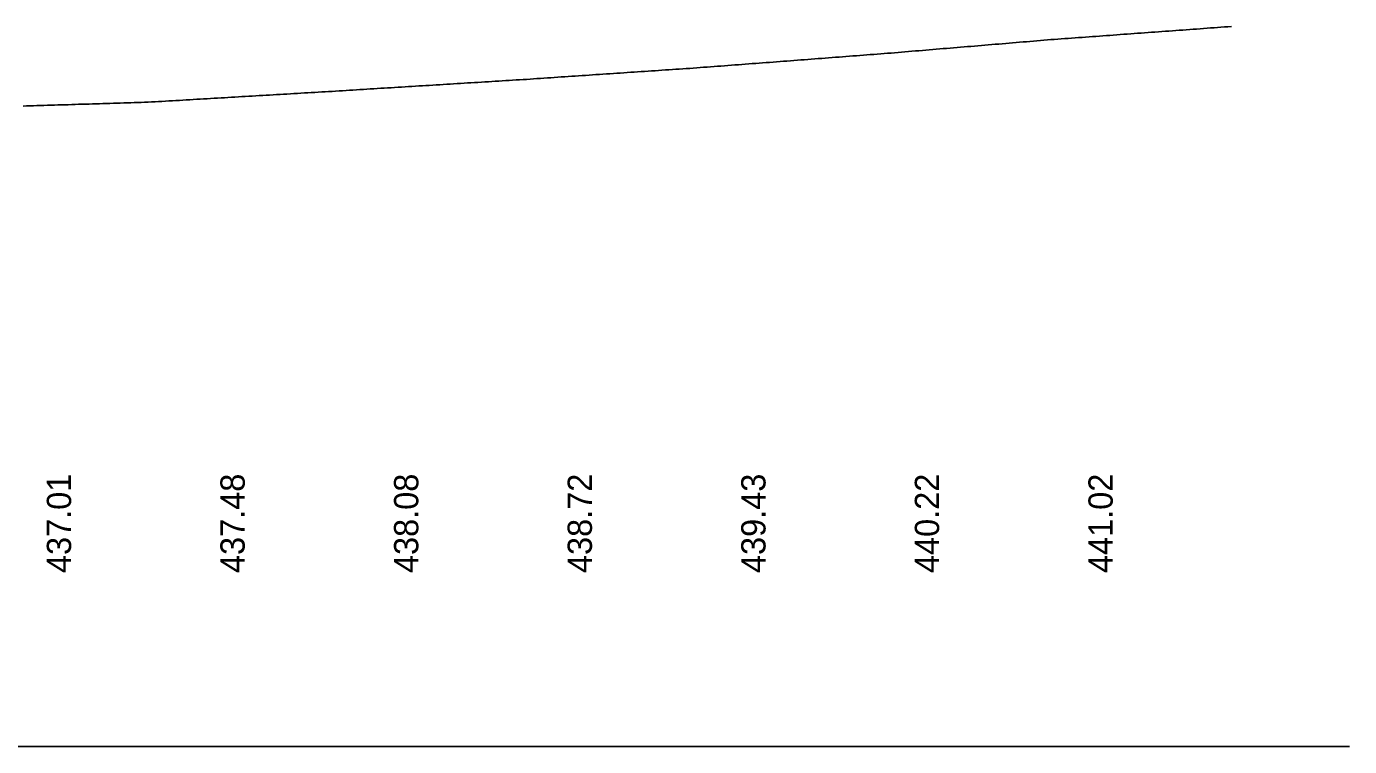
# Model space of a CAD drawing. Extents: x 1904865 to 1906752, y 1106408 to 1110518.
# Drawn here: x 1906371.1 to 1906752.2, y 1107657.6 to 1107865.1 of the extents above; entities that cross this region are included whole.
import ezdxf

# ---------------------------------------------------------------- set-up
doc = ezdxf.new("R2010")
doc.units = 0
for name, color, linetype in [('RD_DDB_Profile_EX', 7, 'Continuous'), ('RD_DDB_StripGrade', 7, 'Continuous'), ('RD_GPK_Profile_Cell', 7, 'Continuous')]:
    doc.layers.add(name, color=color, linetype=linetype)

msp = doc.modelspace()

# ---------------------------------------------------------------- linework, layer by layer
at = {"layer": 'RD_DDB_Profile_EX'}
for points in [[(1906652.17, 1107860.13), (1906653.17, 1107860.22), (1906654.17, 1107860.3), (1906655.17, 1107860.38), (1906656.17, 1107860.47), (1906657.17, 1107860.55), (1906658.17, 1107860.63), (1906659.17, 1107860.72), (1906660.17, 1107860.8), (1906661.17, 1107860.89), (1906662.17, 1107860.97), (1906663.17, 1107861.05), (1906664.17, 1107861.14), (1906665.17, 1107861.23), (1906666.17, 1107861.31), (1906667.17, 1107861.38), (1906668.17, 1107861.46), (1906669.17, 1107861.53), (1906670.17, 1107861.6), (1906671.17, 1107861.68), (1906672.17, 1107861.75), (1906673.17, 1107861.82), (1906674.17, 1107861.89), (1906675.17, 1107861.97), (1906676.17, 1107862.04), (1906677.17, 1107862.11), (1906678.17, 1107862.19), (1906679.17, 1107862.26), (1906680.17, 1107862.33), (1906681.17, 1107862.4), (1906682.17, 1107862.48), (1906683.17, 1107862.55), (1906684.17, 1107862.62), (1906685.17, 1107862.7), (1906686.17, 1107862.77), (1906687.17, 1107862.84), (1906688.17, 1107862.92), (1906689.17, 1107862.99), (1906690.17, 1107863.06), (1906691.17, 1107863.13), (1906692.17, 1107863.21), (1906693.17, 1107863.28), (1906694.17, 1107863.35), (1906695.17, 1107863.43), (1906696.17, 1107863.5), (1906697.17, 1107863.57), (1906698.17, 1107863.65), (1906699.17, 1107863.72), (1906700.17, 1107863.79), (1906701.17, 1107863.86), (1906702.17, 1107863.94), (1906703.17, 1107864.01), (1906704.17, 1107864.08), (1906705.17, 1107864.16), (1906706.17, 1107864.23), (1906707.17, 1107864.3), (1906708.17, 1107864.37), (1906709.17, 1107864.45), (1906710.17, 1107864.52), (1906711.17, 1107864.59), (1906712.17, 1107864.67), (1906713.17, 1107864.74), (1906714.17, 1107864.81), (1906715.17, 1107864.89), (1906716.17, 1107864.96), (1906717.17, 1107865.03), (1906718.17, 1107865.11), (1906718.22, 1107865.11)], [(1906552.17, 1107852.36), (1906553.17, 1107852.43), (1906554.17, 1107852.5), (1906555.17, 1107852.57), (1906556.17, 1107852.63), (1906557.17, 1107852.7), (1906558.17, 1107852.77), (1906559.17, 1107852.84), (1906560.17, 1107852.9), (1906561.17, 1107852.97), (1906562.17, 1107853.04), (1906563.17, 1107853.11), (1906564.17, 1107853.17), (1906565.17, 1107853.25), (1906566.17, 1107853.33), (1906567.17, 1107853.4), (1906568.17, 1107853.48), (1906569.17, 1107853.55), (1906570.17, 1107853.63), (1906571.17, 1107853.71), (1906572.17, 1107853.78), (1906573.17, 1107853.86), (1906574.17, 1107853.93), (1906575.17, 1107854.01), (1906576.17, 1107854.09), (1906577.17, 1107854.16), (1906578.17, 1107854.24), (1906579.17, 1107854.32), (1906580.17, 1107854.39), (1906581.17, 1107854.47), (1906582.17, 1107854.54), (1906583.17, 1107854.62), (1906584.17, 1107854.7), (1906585.17, 1107854.77), (1906586.17, 1107854.85), (1906587.17, 1107854.92), (1906588.17, 1107855), (1906589.17, 1107855.08), (1906590.17, 1107855.15), (1906591.17, 1107855.23), (1906592.17, 1107855.3), (1906593.17, 1107855.38), (1906594.17, 1107855.46), (1906595.17, 1107855.53), (1906596.17, 1107855.61), (1906597.17, 1107855.68), (1906598.17, 1107855.76), (1906599.17, 1107855.84), (1906600.17, 1107855.91), (1906601.17, 1107855.99), (1906602.17, 1107856.06), (1906603.17, 1107856.14), (1906604.17, 1107856.22), (1906605.17, 1107856.29), (1906606.17, 1107856.37), (1906607.17, 1107856.45), (1906608.17, 1107856.52), (1906609.17, 1107856.6), (1906610.17, 1107856.67), (1906611.17, 1107856.75), (1906612.17, 1107856.83), (1906613.17, 1107856.9), (1906614.17, 1107856.98), (1906615.17, 1107857.05), (1906616.17, 1107857.13), (1906617.17, 1107857.21), (1906618.17, 1107857.29), (1906619.17, 1107857.37), (1906620.17, 1107857.45), (1906621.17, 1107857.54), (1906622.17, 1107857.62), (1906623.17, 1107857.71), (1906624.17, 1107857.79), (1906625.17, 1107857.87), (1906626.17, 1107857.96), (1906627.17, 1107858.04), (1906628.17, 1107858.12), (1906629.17, 1107858.21), (1906630.17, 1107858.29), (1906631.17, 1107858.37), (1906632.17, 1107858.46), (1906633.17, 1107858.54), (1906634.17, 1107858.63), (1906635.17, 1107858.71), (1906636.17, 1107858.79), (1906637.17, 1107858.88), (1906638.17, 1107858.96), (1906639.17, 1107859.04), (1906640.17, 1107859.13), (1906641.17, 1107859.21), (1906642.17, 1107859.3), (1906643.17, 1107859.38), (1906644.17, 1107859.46), (1906645.17, 1107859.55), (1906646.17, 1107859.63), (1906647.17, 1107859.71), (1906648.17, 1107859.8), (1906649.17, 1107859.88), (1906650.17, 1107859.96), (1906651.17, 1107860.05), (1906652.17, 1107860.13)], [(1906452.17, 1107845.99), (1906453.17, 1107846.05), (1906454.17, 1107846.11), (1906455.17, 1107846.17), (1906456.17, 1107846.23), (1906457.17, 1107846.29), (1906458.17, 1107846.35), (1906459.17, 1107846.41), (1906460.17, 1107846.47), (1906461.17, 1107846.53), (1906462.17, 1107846.59), (1906463.17, 1107846.66), (1906464.17, 1107846.72), (1906465.17, 1107846.78), (1906466.17, 1107846.84), (1906467.17, 1107846.9), (1906468.17, 1107846.97), (1906469.17, 1107847.03), (1906470.17, 1107847.09), (1906471.17, 1107847.15), (1906472.17, 1107847.21), (1906473.17, 1107847.28), (1906474.17, 1107847.34), (1906475.17, 1107847.4), (1906476.17, 1107847.46), (1906477.17, 1107847.52), (1906478.17, 1107847.59), (1906479.17, 1107847.65), (1906480.17, 1107847.71), (1906481.17, 1107847.77), (1906482.17, 1107847.83), (1906483.17, 1107847.9), (1906484.17, 1107847.96), (1906485.17, 1107848.02), (1906486.17, 1107848.08), (1906487.17, 1107848.14), (1906488.17, 1107848.21), (1906489.17, 1107848.27), (1906490.17, 1107848.33), (1906491.17, 1107848.39), (1906492.17, 1107848.45), (1906493.17, 1107848.51), (1906494.17, 1107848.57), (1906495.17, 1107848.64), (1906496.17, 1107848.7), (1906497.17, 1107848.76), (1906498.17, 1107848.82), (1906499.17, 1107848.88), (1906500.17, 1107848.94), (1906501.17, 1107849), (1906502.17, 1107849.07), (1906503.17, 1107849.13), (1906504.17, 1107849.19), (1906505.17, 1107849.25), (1906506.17, 1107849.31), (1906507.17, 1107849.37), (1906508.17, 1107849.43), (1906509.17, 1107849.5), (1906510.17, 1107849.56), (1906511.17, 1107849.62), (1906512.17, 1107849.68), (1906513.17, 1107849.74), (1906514.17, 1107849.81), (1906515.17, 1107849.87), (1906516.17, 1107849.94), (1906517.17, 1107850.01), (1906518.17, 1107850.08), (1906519.17, 1107850.14), (1906520.17, 1107850.21), (1906521.17, 1107850.28), (1906522.17, 1107850.35), (1906523.17, 1107850.41), (1906524.17, 1107850.48), (1906525.17, 1107850.55), (1906526.17, 1107850.61), (1906527.17, 1107850.68), (1906528.17, 1107850.75), (1906529.17, 1107850.82), (1906530.17, 1107850.88), (1906531.17, 1107850.95), (1906532.17, 1107851.02), (1906533.17, 1107851.09), (1906534.17, 1107851.15), (1906535.17, 1107851.22), (1906536.17, 1107851.29), (1906537.17, 1107851.36), (1906538.17, 1107851.42), (1906539.17, 1107851.49), (1906540.17, 1107851.56), (1906541.17, 1107851.62), (1906542.17, 1107851.69), (1906543.17, 1107851.76), (1906544.17, 1107851.83), (1906545.17, 1107851.89), (1906546.17, 1107851.96), (1906547.17, 1107852.03), (1906548.17, 1107852.1), (1906549.17, 1107852.16), (1906550.17, 1107852.23), (1906551.17, 1107852.3), (1906552.17, 1107852.36)], [(1906370.17, 1107842.16), (1906371.17, 1107842.19), (1906372.17, 1107842.23), (1906373.17, 1107842.26), (1906374.17, 1107842.29), (1906375.17, 1107842.32), (1906376.17, 1107842.35), (1906377.17, 1107842.38), (1906378.17, 1107842.41), (1906379.17, 1107842.45), (1906380.17, 1107842.48), (1906381.17, 1107842.51), (1906382.17, 1107842.54), (1906383.17, 1107842.57), (1906384.17, 1107842.6), (1906385.17, 1107842.63), (1906386.17, 1107842.67), (1906387.17, 1107842.7), (1906388.17, 1107842.73), (1906389.17, 1107842.76), (1906390.17, 1107842.79), (1906391.17, 1107842.82), (1906392.17, 1107842.85), (1906393.17, 1107842.89), (1906394.17, 1107842.92), (1906395.17, 1107842.95), (1906396.17, 1107842.98), (1906397.17, 1107843.01), (1906398.17, 1107843.04), (1906399.17, 1107843.07), (1906400.17, 1107843.11), (1906401.17, 1107843.14), (1906402.17, 1107843.17), (1906403.17, 1107843.2), (1906404.17, 1107843.23), (1906405.17, 1107843.27), (1906406.17, 1107843.31), (1906407.17, 1107843.34), (1906408.17, 1107843.4), (1906409.17, 1107843.46), (1906410.17, 1107843.52), (1906411.17, 1107843.58), (1906412.17, 1107843.64), (1906413.17, 1107843.7), (1906414.17, 1107843.76), (1906415.17, 1107843.81), (1906416.17, 1107843.87), (1906417.17, 1107843.93), (1906418.17, 1107843.99), (1906419.17, 1107844.05), (1906420.17, 1107844.11), (1906421.17, 1107844.17), (1906422.17, 1107844.23), (1906423.17, 1107844.29), (1906424.17, 1107844.35), (1906425.17, 1107844.4), (1906426.17, 1107844.46), (1906427.17, 1107844.52), (1906428.17, 1107844.58), (1906429.17, 1107844.64), (1906430.17, 1107844.7), (1906431.17, 1107844.76), (1906432.17, 1107844.82), (1906433.17, 1107844.88), (1906434.17, 1107844.93), (1906435.17, 1107844.99), (1906436.17, 1107845.05), (1906437.17, 1107845.11), (1906438.17, 1107845.17), (1906439.17, 1107845.23), (1906440.17, 1107845.29), (1906441.17, 1107845.35), (1906442.17, 1107845.41), (1906443.17, 1107845.46), (1906444.17, 1107845.52), (1906445.17, 1107845.58), (1906446.17, 1107845.64), (1906447.17, 1107845.7), (1906448.17, 1107845.76), (1906449.17, 1107845.82), (1906450.17, 1107845.88), (1906451.17, 1107845.94), (1906452.17, 1107845.99)]]:
    msp.add_lwpolyline(points, dxfattribs=at)
at = {"layer": 'RD_GPK_Profile_Cell'}
msp.add_line((1905252.2, 1107657.6), (1906752.2, 1107657.6), dxfattribs=at)

# ---------------------------------------------------------------- texts
at = {"layer": 'RD_DDB_StripGrade'}
for s, p in [('437.01', (1906384, 1107707.6)), ('437.48', (1906434, 1107707.6)), ('438.08', (1906484, 1107707.6)), ('438.72', (1906534, 1107707.6)), ('439.43', (1906584, 1107707.6)), ('440.22', (1906634, 1107707.6)), ('441.02', (1906684, 1107707.6))]:
    msp.add_text(s, height=7, rotation=90, dxfattribs=at).set_placement(p)

doc.saveas('drawing.dxf')
